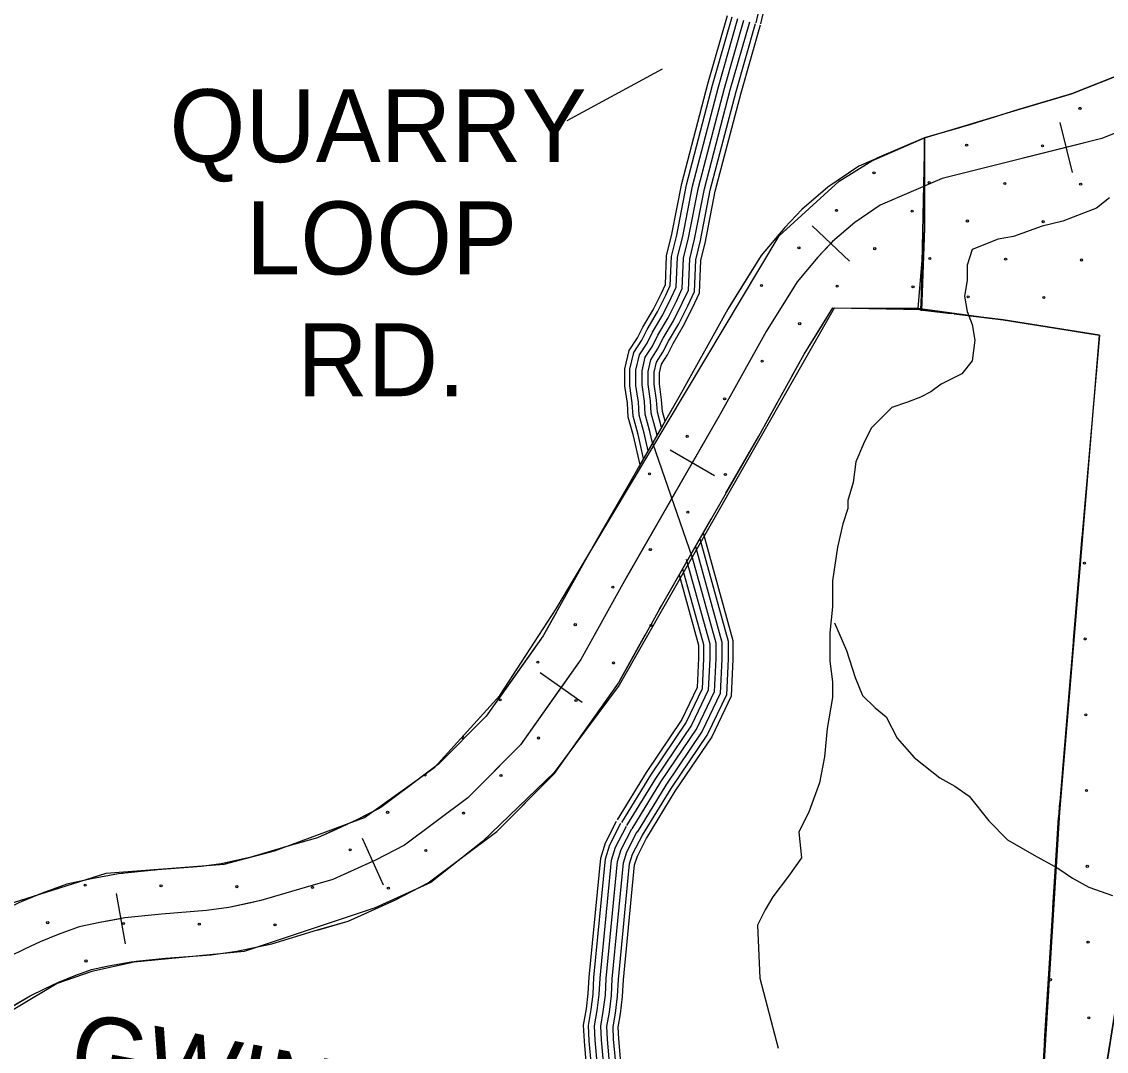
# Model space of a CAD drawing. Extents: x 1788175 to 1969470, y 584502 to 738744.
# Drawn here: x 1836129 to 1841632, y 684158 to 689382 of the extents above; entities that cross this region are included whole.
import ezdxf

# ---------------------------------------------------------------- set-up
doc = ezdxf.new("R2010")
doc.units = 0
for name, color, linetype in [('DESIGN - CONTOURS - Intermediate with optional Text', 7, 'Continuous'), ('DESIGN - EROSION CONTROL - Devices', 7, 'Continuous'), ('DESIGN - ROW - Right-of-Way and Easement Labels', 7, 'Continuous'), ('DESIGN - SCRATCH - User 1', 7, 'Continuous'), ('DESIGN - TRANSPORTATION - Text', 7, 'Continuous'), ('SURVEY - DRAINAGE - Area Shapes', 7, 'Continuous'), ('SURVEY - TRANSPORTATION - Roads', 7, 'Continuous'), ('SURVEY - VEGETATION - Features with Text', 7, 'Continuous')]:
    doc.layers.add(name, color=color, linetype=linetype)

msp = doc.modelspace()

# ---------------------------------------------------------------- linework, layer by layer
at = {"layer": 'DESIGN - CONTOURS - Intermediate with optional Text'}
for p, q in [((1841396.7, 688870.2), (1841459.8, 688618)), ((1840139.9, 688346.3), (1840328.7, 688167.6)), ((1839419, 687209.4), (1839644.5, 687079.9)), ((1838760.4, 686080.8), (1838972.4, 685930.3)), ((1837856.1, 685239.7), (1837962.6, 685002.5)), ((1836608.3, 684959.4), (1836653.9, 684703.4))]:
    msp.add_line(p, q, dxfattribs=at)
for points in [[(1846186.4, 693943.2), (1845882, 693808.2), (1845529.7, 693618.9), (1845463.9, 693515.6), (1845357.2, 693316.3), (1843618.5, 690558.3), (1843041.4, 689778.8), (1842899, 689636.4), (1842786.6, 689509), (1842681.6, 689411.6), (1842501.8, 689269.2), (1842306.9, 689126.8), (1842142, 689029.3), (1841924.7, 688916.9), (1841609.9, 688789.5), (1840799.2, 688586.7)], [(1842042.9, 688978.1), (1841924.7, 688916.9), (1841609.9, 688789.5), (1841428.2, 688744.1)], [(1841428.2, 688744.1), (1840799.2, 688586.7)], [(1840799.2, 688586.7), (1840485.5, 688451.9), (1840356.5, 688363.3), (1840243.4, 688266.6), (1840168.5, 688187.5), (1840063.1, 688062.6), (1839906.1, 687810.3), (1839673.1, 687390.8), (1839178.9, 686530), (1838966.3, 686146.3), (1838659.2, 685713.6), (1838392.1, 685444.6), (1838071.5, 685204.3), (1837924.7, 685128), (1837707.7, 685030.5), (1837567.3, 684990.2), (1837342.7, 684922.9), (1837180.5, 684888.8), (1837066.4, 684872.2), (1836838.4, 684854.9), (1836652.3, 684835.2), (1836526.2, 684812.7), (1836420, 684790), (1836313.7, 684751.2), (1836223.3, 684714.3), (1836146.9, 684679.2), (1836064.5, 684638.1)], [(1840799.2, 688586.7), (1840485.5, 688451.9), (1840356.5, 688363.3), (1840243.4, 688266.6), (1840234.3, 688257)], [(1840234.3, 688257), (1840168.5, 688187.5), (1840063.1, 688062.6), (1839906.1, 687810.3), (1839855.7, 687719.7)], [(1839855.7, 687719.7), (1839673.1, 687390.8), (1839531.8, 687144.7)], [(1839531.8, 687144.7), (1839203.1, 686572.3)], [(1839203.1, 686572.3), (1839178.9, 686530), (1838966.3, 686146.3), (1838866.4, 686005.5)], [(1838866.4, 686005.5), (1838659.2, 685713.6), (1838446.4, 685499.3)], [(1838446.4, 685499.3), (1838392.1, 685444.6), (1838071.5, 685204.3), (1837924.7, 685128), (1837909.4, 685121.1)], [(1837909.4, 685121.1), (1837707.7, 685030.5), (1837567.3, 684990.2), (1837342.7, 684922.9), (1837285.6, 684910.9)], [(1837285.6, 684910.9), (1837180.5, 684888.8), (1837066.4, 684872.2), (1836838.4, 684854.9), (1836652.3, 684835.2), (1836631.1, 684831.4)], [(1836631.1, 684831.4), (1836526.2, 684812.7), (1836420, 684790), (1836313.7, 684751.2), (1836223.3, 684714.3), (1836146.9, 684679.2), (1836064.5, 684638.1), (1836014.7, 684608.6)]]:
    msp.add_lwpolyline(points, dxfattribs=at)
at = {"layer": 'DESIGN - EROSION CONTROL - Devices'}
for centre in [(1841498.8, 688942.5), (1840923.8, 688755.9), (1841308.4, 688752.1), (1840453.7, 688615.4), (1840733.4, 688565.5), (1841118, 688561.7), (1841502.5, 688558), (1840263.3, 688425), (1840647.8, 688421.3), (1840927.5, 688371.3), (1841312.1, 688367.6), (1840072.9, 688234.6), (1840457.4, 688230.9), (1840737.1, 688180.9), (1841121.7, 688177.2), (1841506.2, 688173.4), (1839882.4, 688044.2), (1840267, 688040.5), (1840651.6, 688036.7), (1840931.3, 687986.8), (1841315.8, 687983), (1840076.6, 687850.1), (1839886.2, 687659.6), (1839695.8, 687469.2), (1839505.4, 687278.8), (1839315, 687088.4), (1839699.5, 687084.7), (1839509.1, 686894.3), (1839318.7, 686703.9), (1841521.2, 686635.2), (1839128.3, 686513.5), (1838937.9, 686323), (1839322.4, 686319.3), (1841524.9, 686250.7), (1838747.5, 686132.6), (1839132, 686128.9), (1838557, 685942.2), (1838941.6, 685938.5), (1841528.6, 685866.1), (1838751.2, 685748.1), (1838560.8, 685557.7), (1841532.4, 685481.6), (1837985.8, 685371), (1838370.4, 685367.3), (1837795.4, 685180.6), (1838180, 685176.9), (1841536.1, 685097), (1836451.3, 685001.4), (1836835.9, 684997.6), (1837220.4, 684993.9), (1837605, 684990.2), (1837989.6, 684986.4), (1836260.9, 684811), (1836645.5, 684807.2), (1837030, 684803.5), (1837414.6, 684799.8), (1841539.8, 684712.5), (1836455.1, 684616.8), (1841349.4, 684522.1), (1841543.6, 684327.9)]:
    msp.add_circle(centre, 5.28, dxfattribs=at)
for centre, start, end in [((1838366.6, 685751.8), 200.523, 75.0699), ((1838176.2, 685561.4), 188.4105, 62.902)]:
    msp.add_arc(centre, 5.28, start, end, dxfattribs=at)
at = {"layer": 'DESIGN - ROW - Right-of-Way and Easement Labels'}
msp.add_lwpolyline([(1839379.1, 689140.8), (1838894.9, 688880.2)], dxfattribs=at)
at = {"layer": 'DESIGN - SCRATCH - User 1'}
for points in [[(1841396, 685372.4), (1841516.8, 686810.5), (1841598.6, 687791.7), (1841109, 687870.4), (1840690.6, 687921.2), (1840709.7, 688332.9), (1840710.4, 688793.4), (1841182.2, 688934.8), (1841456.1, 689016.3), (1841737.5, 689127.5), (1841959.7, 689253.5), (1842115.2, 689409.1)], [(1836087.5, 684913.5), (1836558.1, 685061.5), (1837156.4, 685108.6), (1837411.9, 685175.8), (1837869, 685344), (1838225.4, 685599.6), (1838554.8, 685962.9), (1838841.4, 686403), (1839971.8, 688296), (1840277.3, 688573.5), (1840441.9, 688677), (1840710.4, 688793.4), (1840690.6, 687921.2), (1840251.8, 687929.2), (1839160.7, 686016.9), (1838830.4, 685572.7), (1838467.4, 685222.9), (1838205.2, 685014.4), (1837922.8, 684886.6), (1837257.3, 684664.6), (1836699.3, 684610.8), (1836484.1, 684563.7), (1836309.3, 684503.1), (1834565.8, 683460.1)], [(1842496.8, 684944.4), (1841783.2, 685034.5), (1841611.6, 683948.5), (1841447.9, 682896.4), (1841216, 682931.3), (1841318.6, 684109), (1841396, 685372.4)]]:
    msp.add_lwpolyline(points, dxfattribs=at)
at = {"layer": 'DESIGN - TRANSPORTATION - Text'}
for points in [[(1841648.1, 688489.3), (1841582.4, 688436.7), (1841516.7, 688410.5), (1841411.7, 688371.1), (1841306.6, 688344.8), (1841162.1, 688292.2), (1841083.3, 688279.1), (1840951.9, 688226.6), (1840925.6, 688147.8), (1840925.6, 688068.9), (1840912.5, 687990.1), (1840925.6, 687911.3), (1840951.9, 687845.6), (1840965, 687766.8), (1840951.9, 687661.7), (1840899.4, 687596.1), (1840794.3, 687543.5), (1840741.7, 687504.1), (1840689.2, 687477.8), (1840623.5, 687451.6), (1840544.7, 687425.3), (1840492.2, 687372.7), (1840439.6, 687320.2), (1840400.2, 687241.4), (1840360.8, 687149.4), (1840347.7, 687044.4), (1840321.4, 686952.4), (1840321.4, 686913), (1840295.1, 686834.2), (1840268.9, 686716), (1840242.6, 686545.2), (1840242.6, 686413.8), (1840229.5, 686282.5), (1840229.5, 686138), (1840242.6, 686032.9), (1840242.6, 685954.1), (1840216.3, 685796.5), (1840203.2, 685652), (1840176.9, 685520.6), (1840124.4, 685376.1), (1840071.8, 685271), (1840085, 685139.7), (1840019.3, 685047.7), (1839940.5, 684942.6), (1839901.1, 684877), (1839861.7, 684798.2), (1839874.8, 684528.9), (1839966.7, 684174.2)], [(1840252.6, 686332.1), (1840314.3, 686191.8), (1840357.3, 686055.4), (1840394.5, 685963), (1840460, 685900.5), (1840515.6, 685856.1), (1840570.8, 685747.6), (1840658, 685648.9), (1840787.1, 685545.9), (1840864.6, 685503.3), (1840936.2, 685452.7), (1841037.2, 685327.9), (1841130.4, 685231.2), (1841265.6, 685154.1), (1841387, 685087.2), (1841460.5, 685036.6), (1841544.1, 684992), (1841663.7, 684949.1)]]:
    msp.add_lwpolyline(points, dxfattribs=at)
at = {"layer": 'SURVEY - DRAINAGE - Area Shapes'}
msp.add_lwpolyline([(1839330.2, 687245.4), (1839531.2, 686663.6)], dxfattribs=at)
at = {"layer": 'SURVEY - TRANSPORTATION - Roads'}
for points in [[(1840221.2, 690933.1), (1840194.2, 690899.5), (1840169.5, 690834.2), (1840131.9, 690690), (1840043.3, 690341.8), (1839952.8, 689806.8), (1839853.6, 689376.5)], [(1840240.5, 690917.6), (1840215.9, 690887), (1840193.1, 690826.7), (1840155.8, 690683.9), (1840067.5, 690336.7), (1839977.1, 689802), (1839877.7, 689371)], [(1839266.7, 687134.8), (1839232.8, 687281.6), (1839206.9, 687376.7), (1839202.6, 687446.2), (1839190.2, 687533.1), (1839190.2, 687621.4), (1839211.9, 687713.8), (1839253.5, 687778.5), (1839280.8, 687833.2), (1839332.8, 687921.3), (1839375, 688005.7), (1839395.2, 688049.1), (1839401.5, 688195.2), (1839428.5, 688304.9), (1839478.1, 688560.9), (1839610.7, 689067.3), (1839709.8, 689414.3)], [(1839284.8, 687166.3), (1839256.8, 687287.7), (1839231.4, 687380.8), (1839227.2, 687448.8), (1839214.9, 687534.8), (1839214.9, 687618.6), (1839235, 687704), (1839275, 687766.3), (1839302.5, 687821.3), (1839354.5, 687909.5), (1839397.2, 687995), (1839419.7, 688043.1), (1839426.1, 688191.7), (1839452.7, 688299.6), (1839502.2, 688555.5), (1839634.6, 689060.7), (1839733.6, 689407.5)], [(1839307.5, 687205.9), (1839286.9, 687295.2), (1839262.2, 687385.9), (1839258.1, 687451.9), (1839245.9, 687537), (1839245.9, 687615), (1839264, 687691.8), (1839302, 687750.9), (1839329.7, 687806.5), (1839381.8, 687894.7), (1839425.2, 687981.5), (1839450.4, 688035.6), (1839457, 688187.2), (1839483, 688292.9), (1839532.4, 688548.6), (1839664.5, 689052.6), (1839763.4, 689399)], [(1839330.2, 687245.4), (1839316.9, 687302.8), (1839292.9, 687391), (1839288.9, 687455.1), (1839276.9, 687539.2), (1839276.9, 687611.4), (1839292.9, 687679.5), (1839329, 687735.6), (1839357, 687791.7), (1839409, 687879.9), (1839453.1, 687968), (1839481.1, 688028.1), (1839487.8, 688182.8), (1839513.2, 688286.3), (1839562.6, 688541.7), (1839694.4, 689044.4), (1839793.2, 689390.5)], [(1839330.2, 687245.4), (1839316.9, 687302.8), (1839292.9, 687391), (1839288.9, 687455.1), (1839276.9, 687539.2), (1839276.9, 687611.4), (1839292.9, 687679.5), (1839329, 687735.6), (1839357, 687791.7), (1839409, 687879.9), (1839453.1, 687968), (1839481.1, 688028.1), (1839487.8, 688182.8), (1839513.2, 688286.3), (1839562.7, 688541.7), (1839694.4, 689044.4), (1839793.2, 689390.5)], [(1839352.9, 687284.9), (1839347, 687310.4), (1839323.7, 687396.1), (1839319.8, 687458.2), (1839307.9, 687541.4), (1839307.9, 687607.8), (1839321.9, 687667.2), (1839355.9, 687720.2), (1839384.2, 687776.9), (1839436.3, 687865), (1839481, 687954.5), (1839511.8, 688020.6), (1839518.6, 688178.4), (1839543.5, 688279.6), (1839592.9, 688534.8), (1839724.3, 689036.2), (1839823, 689382)], [(1839375.4, 687324.1), (1839354.4, 687401.1), (1839350.6, 687461.4), (1839338.9, 687543.6), (1839338.9, 687604.2), (1839350.8, 687654.9), (1839382.9, 687704.9), (1839411.5, 687762), (1839463.5, 687850.2), (1839508.9, 687941.1), (1839542.5, 688013.1), (1839549.5, 688174), (1839573.8, 688273), (1839623.1, 688527.9), (1839754.2, 689028), (1839852.8, 689373.5)], [(1839393.5, 687355.6), (1839379.9, 687405.4), (1839376.2, 687464), (1839364.6, 687545.5), (1839364.6, 687601.2), (1839374.9, 687644.8), (1839405.3, 687692.2), (1839434.1, 687749.7), (1839486.1, 687837.9), (1839532.1, 687929.9), (1839568, 688006.9), (1839575.1, 688170.3), (1839598.9, 688267.4), (1839648.2, 688522.2), (1839779, 689021.2), (1839877.5, 689366.4)], [(1839586.6, 686788.2), (1839738, 686242.7), (1839738, 686148.6), (1839729.1, 685960.8), (1839630.6, 685754.8), (1839443.9, 685478.6), (1839298.8, 685241.9)], [(1839569.3, 686758.1), (1839713.3, 686239.3), (1839713.3, 686149.2), (1839704.6, 685966.9), (1839609.1, 685767.2), (1839423.1, 685492), (1839277.7, 685254.9)], [(1839547.6, 686720.3), (1839682.3, 686235.1), (1839682.3, 686150), (1839673.9, 685974.7), (1839582.2, 685782.6), (1839397.1, 685508.8), (1839251.3, 685271.1)], [(1839501.3, 686655.3), (1839620.3, 686226.6), (1839620.3, 686151.4), (1839612.6, 685990.1), (1839528.2, 685813.5), (1839344.9, 685542.3), (1839198.4, 685303.5)], [(1839531.2, 686663.6), (1839651.3, 686230.8), (1839651.3, 686150.7), (1839643.3, 685982.4), (1839555.2, 685798), (1839371, 685525.6), (1839224.8, 685287.3)], [(1839531.2, 686663.6), (1839651.3, 686230.8), (1839651.3, 686150.7), (1839643.3, 685982.4), (1839555.2, 685798), (1839371, 685525.5), (1839224.8, 685287.3)], [(1839464.5, 686575.7), (1839563.6, 686218.9), (1839563.6, 686152.8), (1839556.5, 686004.2), (1839478.9, 685841.8), (1839297.2, 685573.1), (1839150.1, 685333.2)], [(1839482.5, 686607), (1839589.3, 686222.4), (1839589.3, 686152.2), (1839581.9, 685997.8), (1839501.2, 685828.9), (1839318.9, 685559.1), (1839172, 685319.7)], [(1838700.8, 681249.9), (1838883.5, 683256.4), (1838934.4, 683738.5), (1838956.9, 683879.8), (1838989.5, 684040.4), (1838995.3, 684084.4), (1838984, 684210.5), (1838980.4, 684291.7), (1838994.3, 684373.6), (1839004, 684451.2), (1839008.2, 684534.4), (1839066.8, 685139.2), (1839091, 685215.7), (1839147.6, 685326.7)], [(1838725.5, 681247.7), (1838908.1, 683253.9), (1838958.9, 683735.2), (1838981.3, 683875.4), (1839013.9, 684036.3), (1839020.2, 684083.9), (1839008.7, 684212.2), (1839005.2, 684290.2), (1839018.8, 684370), (1839028.6, 684449), (1839032.8, 684532.5), (1839091.1, 685134.2), (1839113.9, 685206.3), (1839169.6, 685315.5)], [(1838756.3, 681244.9), (1838938.9, 683250.9), (1838989.7, 683731.2), (1839011.8, 683869.9), (1839044.5, 684031.2), (1839051.4, 684083.2), (1839039.6, 684214.2), (1839036.3, 684288.2), (1839049.5, 684365.5), (1839059.6, 684446.3), (1839063.8, 684530.3), (1839121.7, 685128), (1839142.7, 685194.5), (1839197.2, 685301.4)], [(1838787.2, 681242.1), (1838969.8, 683247.9), (1839020.4, 683727.1), (1839042.3, 683864.3), (1839075.1, 684026.1), (1839082.5, 684082.6), (1839070.6, 684216.3), (1839067.5, 684286.3), (1839080.1, 684361), (1839090.5, 684443.6), (1839094.7, 684528), (1839152.2, 685121.7), (1839171.5, 685182.7), (1839224.8, 685287.3)], [(1838787.2, 681242.1), (1838969.8, 683247.9), (1839020.4, 683727.1), (1839042.3, 683864.3), (1839075.1, 684026.1), (1839082.5, 684082.6), (1839070.6, 684216.3), (1839067.5, 684286.3), (1839080.1, 684361), (1839090.5, 684443.6), (1839094.7, 684528), (1839152.2, 685121.7), (1839171.5, 685182.7), (1839224.8, 685287.3)], [(1838818.1, 681239.3), (1839000.6, 683244.8), (1839051.1, 683723), (1839072.8, 683858.8), (1839105.7, 684021), (1839113.7, 684081.9), (1839101.5, 684218.4), (1839098.6, 684284.4), (1839110.8, 684356.5), (1839121.4, 684440.9), (1839125.6, 684525.7), (1839182.8, 685115.5), (1839200.3, 685170.9), (1839252.5, 685273.2)], [(1838848.9, 681236.4), (1839031.5, 683241.8), (1839081.9, 683718.9), (1839103.3, 683853.3), (1839136.2, 684015.9), (1839144.9, 684081.2), (1839132.5, 684220.4), (1839129.7, 684282.5), (1839141.5, 684352), (1839152.3, 684438.2), (1839156.5, 684523.4), (1839213.3, 685109.3), (1839229.1, 685159.1), (1839280.1, 685259.1)], [(1838874.6, 681234.1), (1839057.1, 683239.3), (1839107.4, 683715.6), (1839128.6, 683848.7), (1839161.6, 684011.6), (1839170.8, 684080.7), (1839158.1, 684222.2), (1839155.5, 684280.9), (1839166.9, 684348.2), (1839177.9, 684436), (1839182.2, 684521.6), (1839238.6, 685104.1), (1839253, 685149.3), (1839303, 685247.4)]]:
    msp.add_lwpolyline(points, dxfattribs=at)
at = {"layer": 'SURVEY - VEGETATION - Features with Text'}
for points in [[(1842342.7, 689666.6), (1842115.2, 689409.1), (1841959.7, 689253.5), (1841737.5, 689127.5), (1841456.1, 689016.3), (1841182.2, 688934.8), (1840945.2, 688860.7), (1840710.4, 688793.4)], [(1841541.4, 689050), (1841456.1, 689016.3), (1841291, 688967.2)], [(1841291, 688967.2), (1841182.2, 688934.8), (1841038.5, 688889.9)], [(1840895, 688846.3), (1840710.4, 688793.4)], [(1840710.4, 688793.4), (1840376.4, 688649.9), (1840219.4, 688542.1), (1840088.2, 688429.9), (1840000.7, 688337.5), (1839880.7, 688195.4), (1839712.1, 687924.5), (1839477.2, 687501.4), (1838982.9, 686640.5), (1838775.6, 686266.3), (1838486.5, 685859), (1838244, 685614.8), (1837951.3, 685395.4), (1837826.6, 685330.6), (1837630.1, 685242.4), (1837503.9, 685206.1), (1837287.2, 685141.1), (1837141.1, 685110.4), (1837041.6, 685095.9), (1836818, 685079), (1836620.7, 685058.1), (1836482.9, 685033.5), (1836357.7, 685006.7), (1836232.6, 684961.1), (1836133.7, 684920.7), (1836049.8, 684882.1)], [(1840710.4, 688793.4), (1840467.8, 688689.2)], [(1840710.4, 688793.4), (1840709.7, 688332.9)], [(1840710.4, 688793.4), (1840709.7, 688332.8)], [(1840334.8, 688621.3), (1840219.4, 688542.1), (1840125.1, 688461.5)], [(1840125.1, 688461.5), (1840088.2, 688429.9), (1840000.7, 688337.5), (1839943.8, 688270.1)], [(1840709.7, 688332.9), (1840675.7, 687928.7), (1841109, 687870.4), (1841598.6, 687791.7), (1841509.9, 686782.3), (1841389.1, 685344.2)], [(1840709.7, 688332.8), (1840695.2, 687915.1)], [(1839853.1, 688151.1), (1839713.7, 687927)], [(1835744.3, 684186.7), (1836172.2, 684440.4), (1836244.1, 684476.2), (1836312.9, 684507.8), (1836394.8, 684541.3), (1836482.4, 684573.2), (1836569.5, 684591.9), (1836684, 684612.3), (1836858.8, 684630.8), (1837091.1, 684648.4), (1837219.8, 684667.2), (1837398.2, 684704.6), (1837630.7, 684774.3), (1837785.2, 684818.7), (1838022.7, 684925.4), (1838191.6, 685013.2), (1838540.2, 685274.4), (1838832, 685568.2), (1839157, 686026.3), (1839374.8, 686419.5), (1839869, 687280.1), (1840100.1, 687696.2), (1840245.5, 687929.9), (1840675.7, 687928.7)], [(1839713.7, 687927), (1839712.1, 687924.5), (1839585.4, 687696.2)], [(1840169.7, 687808.1), (1840245.5, 687929.9), (1840366, 687929.6)], [(1840516, 687929.1), (1840675.7, 687928.7)], [(1840685.9, 687920.7), (1840845.7, 687902.1)], [(1840860.6, 687900.3), (1841109, 687870.4), (1841122.9, 687868.2)], [(1841271, 687844.4), (1841531.6, 687802.5)], [(1840035.9, 687580.6), (1840100.1, 687696.2), (1840169.7, 687808.1)], [(1841531.6, 687802.5), (1841598.6, 687791.7), (1841581.4, 687596.3)], [(1839512.5, 687565.1), (1839477.2, 687501.4), (1839382, 687335.6)], [(1839834, 687219.1), (1839869, 687280.1), (1839963.1, 687449.4)], [(1841568.3, 687446.9), (1841545.2, 687183.9)], [(1839382, 687335.6), (1839250.5, 687106.7)], [(1839702.5, 686990.2), (1839834, 687219.1)], [(1841545.2, 687183.9), (1841522.1, 686920.9)], [(1839175.8, 686976.6), (1839044.4, 686747.7)], [(1839496.4, 686631.2), (1839627.9, 686860.1)], [(1839044.4, 686747.7), (1838982.9, 686640.5), (1838914.8, 686517.7)], [(1841509, 686771.5), (1841486.9, 686508.4)], [(1839365.2, 686402.1), (1839374.8, 686419.5), (1839496.4, 686631.2)], [(1841486.9, 686508.4), (1841464.8, 686245.3)], [(1838842.1, 686386.5), (1838775.6, 686266.3), (1838702.3, 686163)], [(1839164.6, 686039.9), (1839292.5, 686270.9)], [(1838702.3, 686163), (1838549.5, 685947.7)], [(1841452.2, 686095.9), (1841430.1, 685832.8)], [(1839013.3, 685823.7), (1839157, 686026.3), (1839164.6, 686039.9)], [(1838457.5, 685829.8), (1838271.5, 685642.4)], [(1841430.1, 685832.8), (1841408, 685569.7)], [(1838761, 685496.8), (1838832, 685568.2), (1838926.5, 685701.4)], [(1838271.5, 685642.4), (1838244, 685614.8), (1838064, 685479.8)], [(1838575, 685309.4), (1838761, 685496.8)], [(1841395.5, 685420.2), (1841389.1, 685344.2)], [(1837943.1, 685391.1), (1837826.6, 685330.6), (1837705.6, 685276.2)], [(1842519.4, 684941.3), (1841783.2, 685034.5), (1841604.7, 683920.2), (1841440.9, 682868.1), (1841209.1, 682903), (1841311.7, 684080.7), (1841389.1, 685344.2)], [(1841377.2, 685150.8), (1841389.1, 685344.2)], [(1837705.6, 685276.2), (1837630.1, 685242.4), (1837503.9, 685206.1), (1837456, 685191.7)], [(1838248.4, 685055.7), (1838459.7, 685214)], [(1837312.3, 685148.7), (1837287.2, 685141.1), (1837141.1, 685110.4), (1837053.6, 685097.7)], [(1841361.1, 684887.3), (1841377.2, 685150.8)], [(1837053.6, 685097.7), (1837041.6, 685095.9), (1836818, 685079), (1836790.5, 685076.1)], [(1836641.3, 685060.3), (1836620.7, 685058.1), (1836482.9, 685033.5), (1836381.9, 685011.9)], [(1838020.3, 684924.3), (1838022.7, 684925.4), (1838191.6, 685013.2), (1838248.4, 685055.7)], [(1836381.9, 685011.9), (1836357.7, 685006.7), (1836232.6, 684961.1), (1836134.4, 684921)], [(1837635, 684775.5), (1837785.2, 684818.7), (1837883.4, 684862.8)], [(1837381.7, 684701.2), (1837398.2, 684704.6), (1837630.7, 684774.3), (1837635, 684775.5)], [(1841335.8, 684474), (1841351.9, 684737.5)], [(1836710.1, 684615), (1836858.8, 684630.8), (1836973, 684639.5)], [(1836973, 684639.5), (1837091.1, 684648.4), (1837219.8, 684667.2), (1837234.9, 684670.3)], [(1836312.3, 684507.6), (1836312.9, 684507.8), (1836394.8, 684541.3), (1836482.4, 684573.2), (1836562.2, 684590.3)], [(1836078.8, 684385), (1836172.2, 684440.4), (1836244.1, 684476.2), (1836312.3, 684507.6)], [(1841319.6, 684210.5), (1841335.8, 684474)]]:
    msp.add_lwpolyline(points, dxfattribs=at)

# ---------------------------------------------------------------- texts
at = {"layer": 'DESIGN - ROW - Right-of-Way and Easement Labels'}
for s, p in [('QUARRY', (1836878.9, 688669.7)), ('LOOP', (1837267.9, 688100.4)), ('RD.', (1837527.3, 687482.2))]:
    msp.add_text(s, height=370, dxfattribs=at).set_placement(p)
msp.add_text('GWIN', height=370, rotation=349.1773, dxfattribs=at).set_placement((1836353.8, 683998.1))

doc.saveas('drawing.dxf')
